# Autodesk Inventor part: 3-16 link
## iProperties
Author: Administrator
Shininess: 0.0
PropertySet Name: _Private Model Information
Length Units: 11272
Angle Units: 11286
Time Units: 11279
Mass Units: 11290
Length Display Precision: 3
Angle Display Precision: 2
Compacted: True
Created: 2000-09
Part Number: 3-16 link
Document SubType Name: Modeling
Designer: Administrator
Control State: 0
Master: False
Checked Out: False
PropertySet Name: Design Tracking Control
Density: 0.0
Volumn: 0.0
Area: 0.0
PropertySet Name: Model Information
